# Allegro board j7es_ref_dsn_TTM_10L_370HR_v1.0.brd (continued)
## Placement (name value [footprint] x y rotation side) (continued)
R1125  10K  [R402-25]  159.64 132.83 90 bottom
R1126  10K  [R402-25]  158.62 132.83 90 bottom
R1127  47  [R402-25]  194.56 118.23 270 bottom
R1130  40.2K  [R402-25]  194.06 116.58 180 bottom
R1131  1K  [R402-25]  151.76 10.4 90 bottom
R1132  10K  [R402-25]  192.41 117.08 90 bottom
R1133  158K  [R402-25]  163.32 127.37 90 bottom
R1134  10K  [R402-25]  159.13 129.28 0 bottom
R1135  10K  [R402-25]  191.26 117.08 90 bottom
R1136  3.01  [R402-25]  186.56 123.69 270 bottom
R1137  3.0  [R402-25]  185.93 118.99 0 bottom
R1138  3.01  [R402-25]  185.42 123.69 270 bottom
R1139  0  [R402-25]  189.99 97.14 90 bottom
R1140  0  [R402-25]  191.13 97.14 270 bottom
R1141  100K  [R402-25]  195.83 100.32 0 bottom
R1142  10K  [R402-25]  195.71 102.1 0 bottom
R1143  NP  [R402-25]  196.72 103.62 0 bottom
R1144  0  [R402-25]  188.98 104.51 270 bottom
R1145  3.3  [R402-25]  190.12 104.51 90 bottom
R1146  10K  [R402-25]  195.07 104.51 90 bottom
R1147  42.2K  [R402-25]  192.15 105.78 270 bottom
R1152  1.0  [R1206-40X70]  183.26 109.34 90 bottom
R1164  10K  [R402-25]  140.33 148.33 0 top
R1188  47K  [R402-25]  152.15 87.37 180 bottom
R1189  47K  [R402-25]  152.15 90.03 180 bottom
R1190  47K  [R402-25]  152.02 83.05 180 bottom
R1191  47K  [R402-25]  151.13 80.25 0 bottom
R1192  1K  [R402-25]  150.88 85.97 0 bottom
R1196  47K  [R402-25]  149.35 83.05 180 bottom
R1197  47K  [R402-25]  149.22 90.03 180 bottom
R1198  47K  [R402-25]  149.1 80.25 180 bottom
R1200  47K  [R402-25]  148.21 85.33 180 bottom
R1201  47K  [R402-25]  148.21 87.37 0 bottom
R1203  0  [R402-25]  146.81 84.7 270 bottom
R1204  NP  [R402-25]  145.8 84.7 90 bottom
R1205  0  [R402-25]  52.58 58.54 0 bottom
R1206  4.7K  [R402-25]  52.58 59.81 0 bottom
R1207  4.7K  [R402-25]  52.58 61.08 0 bottom
R1208  4.7K  [R402-25]  52.58 54.6 0 bottom
R1209  4.7K  [R402-25]  52.58 57.27 0 bottom
R1219  4.7K  [R402-25]  46.23 55.36 180 bottom
R1221  4.7K  [R402-25]  43.56 56.63 180 bottom
R2008  1K  [R201-6P6SPC]  33.53 24.25 270 bottom
R2020  2.49K  [R402-25]  49.4 36.06 90 top
R2021  2.49K  [R402-25]  48.13 36.06 90 top
R2024  27  [R402-25]  38.1 38.34 0 top
R2025  1K  [R402-25]  27.56 41.14 270 top
R2026  NP-0  [R402-25]  52.58 43.8 90 top
R2027  1K  [R402-25]  27.56 43.8 90 top
R2030  27  [R402-25]  38.1 46.6 0 top
R2032  10K  [R402-25]  28.32 48.12 180 top
R2058  NP-0  [R402-25]  46.86 26.41 180 top
R2059  NP-0  [R402-25]  46.86 27.68 180 top
R2098  62  [R1206-40X70]  29.08 29.33 0 bottom
R2099  3.32K  [R402-25]  32.38 29.71 90 bottom
R2100  100  [R402-25]  33.66 29.71 90 bottom
R2101  33.2K  [R402-25]  34.92 29.71 90 bottom
R2102  100  [R402-25]  42.54 31.87 270 bottom
R2103  10K  [R402-25]  42.54 29.71 90 bottom
R2104  62  [R1206-40X70]  29.08 31.61 180 bottom
R2105  10K  [R402-25]  34.92 32.37 90 bottom
R2106  100  [R402-25]  32.38 35.04 270 bottom
R2107  100K  [R402-25]  33.66 35.04 90 bottom
R2108  100  [R402-25]  34.92 35.04 270 bottom
R2109  100  [R402-25]  37.46 35.04 90 bottom
R2110  100  [R402-25]  41.27 35.04 90 bottom
R2111  1.5K  [R402-25]  50.67 48 180 bottom
R2112  3.32K  [R402-25]  44.32 44.19 270 bottom
R2113  3.32K  [R402-25]  45.47 44.19 270 bottom
R2114  3.32K  [R402-25]  46.61 44.19 270 bottom
R2115  240  [R402-25]  50.55 45.71 90 bottom
R2116  3.32K  [R402-25]  51.56 45.71 90 bottom
R3058  4.7K  [RES0402_0-5]  91.24 36.85 180 top
R3059  1.87K_1%  [RES0402_0-5]  91.24 35.36 180 top
R3060  10K  [RES0402_0-5]  95.94 23.62 270 top
R3061  100K  [RES0402_0-5]  128.65 20.1 180 top
R3062  100K  [RES0402_0-5]  130.68 20.1 180 top
R3065  41.2K_1%  [RES0402_0-5]  103.89 16.79 90 top
R3066  41.2K_1%  [RES0402_0-5]  111.51 16.28 90 top
R3067  30.9K_1%  [RES0402_0-5]  112.65 16.28 270 top
R3102  0E  [RES0402_0-5]  99.57 23.48 0 bottom
R3103  0E  [RES0402_0-5]  102.21 23.03 90 bottom
R3104  0E  [RES0402_0-5]  100.97 23.03 90 bottom
R3105  0E  [RES0402_0-5]  115.21 21.95 0 bottom
R3110  10K  [RES0402_0-5]  105.03 16.79 270 bottom
R3111  30.9K_1%  [RES0402_0-5]  103.89 16.79 270 bottom
R3112  61.9K_1%  [RES0402_0-5]  112.65 16.28 270 bottom
R3113  30.1K_1%  [RES0402_0-5]  111.51 16.28 90 bottom
R3114  4.7K  [RES0402_0-5]  106.4 15.98 90 bottom
R3115  0E  [RES0402_0-5]  105.94 14.48 0 bottom
R3118  0E  [RES0402_0-5]  133.49 13.23 90 bottom
R3119  0E  [RES0402_0-5]  132.35 13.23 90 bottom
R3121  100K  [RES0402_0-5]  130.49 12.7 0 bottom
R3122  10K  [R402-25]  151.51 132.96 0 top
R3123  10K  [R402-25]  151.51 134.36 0 top
R3124  49.9  [R402-25]  72.52 19.04 0 bottom
R3125  2K  [R402-25]  85.47 5.7 270 bottom
R3126  4.02K  [R402-25]  64.01 13.96 180 bottom
R3127  2K  [R402-25]  68.71 5.58 270 bottom
R3128  49.9  [R402-25]  65.53 17.26 270 bottom
R3129  4.02K  [R402-25]  47.37 13.83 180 bottom
R3130  2K  [R402-25]  52.07 5.45 270 bottom
R3131  49.9  [R402-25]  62.48 17.26 270 bottom
R3132  4.02K  [R402-25]  30.73 13.83 180 bottom
R3133  2K  [R402-25]  35.56 5.45 270 bottom
R3134  49.9  [R402-25]  56.39 20.06 180 bottom
R3135  0  [R402-25]  52.58 55.62 0 bottom
R3136  0E  [RES0402_0-5]  66.67 49.65 270 top
R3137  0E  [RES0402_0-5]  80.26 49.39 270 bottom
R3138  10K_1%  [RES0201_0-5]  79.25 49.27 90 bottom
R3139  10K_1%  [RES0201_0-5]  77.22 49.27 90 bottom
R3140  10K_1%  [RES0201_0-5]  81.28 49.27 90 bottom
R3141  47K  [R402-25]  154.31 91.3 0 bottom
R3142  22E_1%  [RES0402_0-5]  152.15 91.3 0 bottom
R3143  100  [R402-25]  46.86 57.65 0 bottom
R3144  DNI  [RES0402_0-5]  82.8 104.13 0 bottom
R3145  DNI  [RES0402_0-5]  132.08 84.32 0 top
R3146  DNI  [RES0402_0-5]  132.08 83.3 180 top
R3147  10K_1%  [RES0402_0-5]  127.89 108.45 0 top
R3148  DNI  [RES0402_0-5]  55.63 95.49 180 top
R3149  0E  [RES0402_0-5]  57.66 95.49 0 top
R3150  DNI  [RES0402_0-5]  55.63 98.16 180 top
R3151  0E  [RES0402_0-5]  57.66 98.16 0 top
R*  -  [unnamed#4]  115.82 18.31 180 top
RJ1000  0  [JMP402-25]  177.29 133.85 270 top
RJ1001  1000pF  [JMP402-25]  182.88 115.69 0 top
RJ1013  1000pF  [JMP402-25]  155.32 54.85 180 top
RJ1025  0.A  [JMP402-25]  48.77 56.63 0 bottom
RJ2008  3.32K.A  [JMP402-25]  37.46 31.49 90 bottom
SW2001  PB_SW  [SW4-7914G]  32.38 21.58 180 top
TP35  -  [TP40_SMD]  111 40.76 270 top
TP36  -  [TP40_SMD]  112.9 40.76 270 top
TP37  -  [TP40_SMD]  124.33 36.95 270 top
TP38  -  [TP40_SMD]  124.33 39.61 270 top
TP39  -  [TP40_SMD]  126.24 36.95 270 top
TP40  -  [TP40_SMD]  126.24 39.61 270 top
TP42  -  [TP40_SMD]  116.71 38.22 270 top
TP43  -  [TP40_SMD]  114.81 38.22 270 top
TP105  -  [TP40_SMD]  132.97 78.86 90 top
TP108  -  [TP40_SMD]  53.59 108.19 180 top
TP109  -  [TP40_SMD]  53.59 105.65 180 top
TP115  -  [TP40_SMD]  53.47 100.57 0 top
TP116  -  [TP40_SMD]  41.78 58.66 270 top
TP117  -  [TP40_SMD]  40.77 52.82 0 top
TP127  -  [TP40_SMD]  70.68 74.6 0 top
TP128  -  [TP40_SMD]  125.86 108.45 0 top
TP1000  TP  [TP-30RD13]  179.32 93.84 0 top
TP1001  TP  [TP-30RD13]  197.23 127.12 0 top
TP1002  TP  [TP-30RD13]  171.07 129.66 0 top
TP1003  TP  [TP-30RD13]  157.73 130.29 0 top
TP1004  TP  [TP-30RD13]  159.38 43.04 180 top
TP1005  TP  [TP-30RD13]  185.93 115.43 0 top
TP1006  TP  [TP-30RD13]  186.56 72.38 0 top
TP1008  TP  [TP-30RD13]  179.32 60.44 90 top
TP1010  TP  [TP-30RD13]  195.71 109.59 270 top
TP1012  TP  [TP-30RD13]  184.28 49.65 90 top
TP1013  TP  [TP-30RD13]  164.34 46.85 0 top
TP1016  SMT-TP  [TP1-70X135]  179.58 45.07 90 top
TP1018  TP  [TP-30RD13]  138.56 148.33 0 top
TP1037  TP  [TP-30RD13]  21.08 21.58 0 top
TP1040  TP  [TP-30RD13]  146.3 68.95 0 top
TP2000  TP  [TP-30RD13]  43.69 37.33 90 top
TP3006  -  [TP40_SMD]  97.96 24.01 0 top
TP3014  -  [TP40_SMD]  99.79 25.73 180 bottom
TP3015  -  [TP40_SMD]  102.36 52.69 0 top
TP3016  -  [TP40_SMD]  78.99 125.97 0 top
TP3017  -  [TP40_SMD]  53.47 102.99 0 top
TP3018  -  [TP40_SMD]  76.83 125.97 0 top
TP3019  -  [TP40_SMD]  136.52 84.7 0 top
TP3020  -  [TP40_SMD]  53.47 95.49 0 top
TP3021  -  [TP40_SMD]  53.47 98.16 0 top
TPX1  TP_VIA_MEM0  [TP1-18RD8]  51.31 90.29 0 top
TPX2  TP_VIA_MEM0  [TP1-18RD8]  52.58 86.48 0 top
TPX3  TP_VIA_MEM0  [TP1-18RD8]  48.77 83.94 0 top
TPX4  TP_VIA_MEM0  [TP1-18RD8]  48.77 85.21 0 top
TPX5  TP_VIA_MEM0  [TP1-18RD8]  48.77 81.4 0 top
TPX6  TP_VIA_MEM0  [TP1-18RD8]  50.04 78.86 0 top
TPX7  TP_VIA_MEM0  [TP1-18RD8]  46.23 78.86 0 top
TPX10  TP_VIA_MEM0  [TP1-18RD8]  50.04 77.59 0 top
TPX11  TP_VIA_MEM0  [TP1-18RD8]  65.28 62.35 0 top
TPX12  TP_VIA_MEM0  [TP1-18RD8]  52.58 75.05 0 top
TPX13  TP_VIA_MEM0  [TP1-18RD8]  60.2 50.28 0 top
TPX14  TP_VIA_MEM0  [TP1-18RD8]  62.74 57.27 0 top
TPX15  TP_VIA_MEM0  [TP1-18RD8]  65.28 57.27 0 top
TPX16  TP_VIA_MEM0  [TP1-18RD8]  60.83 69.33 0 top
TPX17  TP_VIA_MEM0  [TP1-18RD8]  39.88 61.71 0 top
TPX18  TP_VIA_MEM0  [TP1-18RD8]  38.61 63.62 0 top
TPX21  TP_VIA_MEM0  [TP1-18RD8]  65.28 48.38 0 top
TPX25  TP_VIA_MEM0  [TP1-18RD8]  47.5 90.29 0 top
TPX26  TP_VIA_MEM0  [TP1-18RD8]  47.5 89.02 0 top
TPX27  TP_VIA_MEM0  [TP1-18RD8]  53.85 85.21 0 top
TPX28  TP_VIA_MEM0  [TP1-18RD8]  48.77 87.75 0 top
TPX29  TP_VIA_MEM0  [TP1-18RD8]  51.31 81.4 0 top
TPX30  TP_VIA_MEM0  [TP1-18RD8]  50.04 81.4 0 top
TPX31  TP_VIA_MEM0  [TP1-18RD8]  50.04 83.94 0 top
TPX32  TP_VIA_MEM0  [TP1-18RD8]  53.85 81.4 0 top
TPX34  TP_VIA_MEM0  [TP1-18RD8]  47.5 78.86 0 top
TPX36  TP_VIA_MEM0  [TP1-18RD8]  56.64 71.87 0 top
TPX37  TP_VIA_MEM0  [TP1-18RD8]  64.01 62.35 0 top
TPX38  TP_VIA_MEM0  [TP1-18RD8]  37.34 64.89 0 top
TPX39  TP_VIA_MEM0  [TP1-18RD8]  70.36 62.35 0 top
TPX41  TP_VIA_MEM0  [TP1-18RD8]  55.12 75.05 0 top
TPX42  TP_VIA_MEM0  [TP1-18RD8]  64.01 60.44 0 top
TPX43  TP_VIA_MEM0  [TP1-18RD8]  61.47 60.44 0 top
TPX44  TP_VIA_MEM0  [TP1-18RD8]  61.47 57.27 0 top
TPX48  TP_VIA_MEM0  [TP1-18RD8]  66.55 52.19 90 top
TPX49  TP_VIA_MEM0  [TP1-18RD8]  48.77 90.29 0 top
TPX50  TP_VIA_MEM0  [TP1-18RD8]  50.04 90.29 0 top
TPX53  TP_VIA_MEM0  [TP1-18RD8]  46.23 85.21 0 top
TPX54  TP_VIA_MEM0  [TP1-18RD8]  53.85 83.94 0 top
TPX55  TP_VIA_MEM0  [TP1-18RD8]  53.85 80.13 0 top
TPX56  TP_VIA_MEM0  [TP1-18RD8]  51.31 82.67 0 top
TPX58  TP_VIA_MEM0  [TP1-18RD8]  47.5 80.13 0 top
TPX59  TP_VIA_MEM0  [TP1-18RD8]  53.85 77.59 0 top
TPX60  TP_VIA_MEM0  [TP1-18RD8]  57.66 75.05 0 top
TPX61  TP_VIA_MEM0  [TP1-18RD8]  64.01 48.38 0 top
TPX62  TP_VIA_MEM0  [TP1-18RD8]  70.99 66.16 0 top
TPX63  TP_VIA_MEM0  [TP1-18RD8]  47.5 82.67 0 top
TPX64  TP_VIA_MEM0  [TP1-18RD8]  60.2 46.47 0 top
TPX65  TP_VIA_MEM0  [TP1-18RD8]  38.61 64.89 0 top
TPX66  TP_VIA_MEM0  [TP1-18RD8]  65.28 58.54 0 top
TPX67  TP_VIA_MEM0  [TP1-18RD8]  71.63 51.55 0 top
TPX68  TP_VIA_MEM0  [TP1-18RD8]  79.76 61.46 0 top
TPX69  TP_VIA_MEM0  [TP1-18RD8]  61.47 52.19 0 top
TPX70  TP_VIA_MEM0  [TP1-18RD8]  61.47 50.28 0 top
TPX72  TP_VIA_MEM0  [TP1-18RD8]  53.85 87.75 0 top
TPX73  TP_VIA_MEM0  [TP1-18RD8]  47.5 86.48 0 top
TPX74  TP_VIA_MEM0  [TP1-18RD8]  48.77 80.13 0 top
TPX75  TP_VIA_MEM0  [TP1-18RD8]  51.31 89.02 0 top
TPX76  TP_VIA_MEM0  [TP1-18RD8]  47.5 85.21 0 top
TPX77  TP_VIA_MEM0  [TP1-18RD8]  46.23 83.94 0 top
TPX78  TP_VIA_MEM0  [TP1-18RD8]  52.58 85.21 0 top
TPX79  TP_VIA_MEM0  [TP1-18RD8]  47.5 81.4 0 top
TPX80  TP_VIA_MEM0  [TP1-18RD8]  62.74 46.47 0 top
TPX81  TP_VIA_MEM0  [TP1-18RD8]  48.77 78.86 0 top
TPX82  TP_VIA_MEM0  [TP1-18RD8]  46.23 75.05 0 top
TPX83  TP_VIA_MEM0  [TP1-18RD8]  53.85 76.32 0 top
TPX84  TP_VIA_MEM0  [TP1-18RD8]  51.31 75.05 0 top
TPX85  TP_VIA_MEM0  [TP1-18RD8]  68.45 64.89 0 top
TPX86  TP_VIA_MEM0  [TP1-18RD8]  69.72 64.89 0 top
TPX87  TP_VIA_MEM0  [TP1-18RD8]  64.01 46.47 0 top
TPX88  TP_VIA_MEM0  [TP1-18RD8]  62.74 48.38 0 top
TPX89  TP_VIA_MEM0  [TP1-18RD8]  39.88 64.89 0 top
TPX90  TP_VIA_MEM0  [TP1-18RD8]  62.74 52.19 0 top
TPX92  TP_VIA_MEM0  [TP1-18RD8]  39.88 58.66 0 top
TPX93  TP_VIA_MEM0  [TP1-18RD8]  65.28 52.19 0 top
TPX94  TP_VIA_MEM0  [TP1-18RD8]  62.74 50.28 0 top
TPX95  TP_VIA_MEM0  [TP1-18RD8]  61.47 48.38 0 top
TPX97  TP_VIA_MEM0  [TP1-18RD8]  47.5 87.75 0 top
TPX98  TP_VIA_MEM0  [TP1-18RD8]  50.04 85.21 0 top
TPX99  TP_VIA_MEM0  [TP1-18RD8]  50.04 86.48 0 top
TPX100  TP_VIA_MEM0  [TP1-18RD8]  52.58 87.75 0 top
TPX101  TP_VIA_MEM0  [TP1-18RD8]  51.31 87.75 0 top
TPX102  TP_VIA_MEM0  [TP1-18RD8]  50.04 82.67 0 top
TPX103  TP_VIA_MEM0  [TP1-18RD8]  51.31 83.94 0 top
TPX104  TP_VIA_MEM0  [TP1-18RD8]  52.58 82.67 0 top
TPX105  TP_VIA_MEM0  [TP1-18RD8]  34.8 49.65 0 top
TPX106  TP_VIA_MEM0  [TP1-18RD8]  37.34 49.65 0 top
TPX107  TP_VIA_MEM0  [TP1-18RD8]  61.47 46.47 0 top
TPX108  TP_VIA_MEM0  [TP1-18RD8]  36.07 49.65 0 top
TPX109  TP_VIA_MEM0  [TP1-18RD8]  56.39 75.05 0 top
TPX110  TP_VIA_MEM0  [TP1-18RD8]  50.04 76.32 0 top
TPX111  TP_VIA_MEM0  [TP1-18RD8]  68.45 66.16 0 top
TPX112  TP_VIA_MEM0  [TP1-18RD8]  43.05 74.41 0 top
TPX113  TP_VIA_MEM0  [TP1-18RD8]  53.85 48.38 0 top
TPX114  TP_VIA_MEM0  [TP1-18RD8]  67.82 58.54 0 top
TPX115  TP_VIA_MEM0  [TP1-18RD8]  71.63 62.35 0 top
TPX116  TP_VIA_MEM0  [TP1-18RD8]  64.01 57.27 0 top
TPX117  TP_VIA_MEM0  [TP1-18RD8]  60.2 52.19 0 top
TPX118  TP_VIA_MEM0  [TP1-18RD8]  64.01 52.19 0 top
TPX121  TP_VIA_MEM0  [TP1-18RD8]  60.2 48.38 0 top
TPX122  TP_VIA_MEM0  [TP1-18RD8]  46.23 89.02 0 top
TPX123  TP_VIA_MEM0  [TP1-18RD8]  53.85 86.48 0 top
TPX124  TP_VIA_MEM0  [TP1-18RD8]  46.23 80.13 0 top
TPX125  TP_VIA_MEM0  [TP1-18RD8]  52.58 89.02 0 top
TPX126  TP_VIA_MEM0  [TP1-18RD8]  48.77 89.02 0 top
TPX127  TP_VIA_MEM0  [TP1-18RD8]  46.23 86.48 0 top
TPX128  TP_VIA_MEM0  [TP1-18RD8]  50.04 80.13 0 top
TPX129  TP_VIA_MEM0  [TP1-18RD8]  47.5 83.94 0 top
TPX130  TP_VIA_MEM0  [TP1-18RD8]  52.58 77.59 0 top
TPX131  TP_VIA_MEM0  [TP1-18RD8]  33.53 49.65 0 top
TPX132  TP_VIA_MEM0  [TP1-18RD8]  52.58 78.86 0 top
TPX133  TP_VIA_MEM0  [TP1-18RD8]  46.23 76.32 0 top
TPX134  TP_VIA_MEM0  [TP1-18RD8]  51.31 76.32 0 top
TPX135  TP_VIA_MEM0  [TP1-18RD8]  48.77 75.05 0 top
TPX136  TP_VIA_MEM0  [TP1-18RD8]  66.55 62.35 0 top
TPX137  TP_VIA_MEM0  [TP1-18RD8]  64.01 50.28 0 top
TPX138  TP_VIA_MEM0  [TP1-18RD8]  41.78 73.14 0 top
TPX139  TP_VIA_MEM0  [TP1-18RD8]  66.55 58.54 0 top
TPX140  TP_VIA_MEM0  [TP1-18RD8]  69.09 62.35 0 top
TPX147  TP_VIA_MEM0  [TP1-18RD8]  89.28 109.59 0 top
TPX148  TP_VIA_MEM0  [TP1-18RD8]  48.77 82.67 0 top
TPX149  TP_VIA_MEM0  [TP1-18RD8]  51.31 85.21 0 top
TPX150  TP_VIA_MEM0  [TP1-18RD8]  50.04 89.02 0 top
TPX151  TP_VIA_MEM0  [TP1-18RD8]  48.77 86.48 0 top
TPX152  TP_VIA_MEM0  [TP1-18RD8]  52.58 80.13 0 top
TPX153  TP_VIA_MEM0  [TP1-18RD8]  51.31 80.13 0 top
TPX154  TP_VIA_MEM0  [TP1-18RD8]  46.23 82.67 0 top
TPX155  TP_VIA_MEM0  [TP1-18RD8]  51.31 78.86 0 top
TPX156  TP_VIA_MEM0  [TP1-18RD8]  36.07 51.55 0 top
TPX157  TP_VIA_MEM0  [TP1-18RD8]  53.85 78.86 0 top
TPX158  TP_VIA_MEM0  [TP1-18RD8]  47.5 76.32 0 top
TPX159  TP_VIA_MEM0  [TP1-18RD8]  51.31 77.59 0 top
TPX160  TP_VIA_MEM0  [TP1-18RD8]  46.23 77.59 0 top
TPX161  TP_VIA_MEM0  [TP1-18RD8]  47.5 75.05 0 top
TPX162  TP_VIA_MEM0  [TP1-18RD8]  70.99 64.89 0 top
TPX163  TP_VIA_MEM0  [TP1-18RD8]  43.05 71.87 0 top
TPX164  TP_VIA_MEM0  [TP1-18RD8]  55.37 70.73 0 top
TPX165  TP_VIA_MEM0  [TP1-18RD8]  67.82 57.27 0 top
TPX166  TP_VIA_MEM0  [TP1-18RD8]  65.28 60.44 0 top
TPX167  TP_VIA_MEM0  [TP1-18RD8]  72.9 62.35 0 top
TPX168  TP_VIA_MEM0  [TP1-18RD8]  67.82 52.19 0 top
TPX173  TP_VIA_MEM0  [TP1-18RD8]  46.23 87.75 0 top
TPX174  TP_VIA_MEM0  [TP1-18RD8]  52.58 83.94 0 top
TPX175  TP_VIA_MEM0  [TP1-18RD8]  53.85 89.02 0 top
TPX176  TP_VIA_MEM0  [TP1-18RD8]  51.31 86.48 0 top
TPX177  TP_VIA_MEM0  [TP1-18RD8]  50.04 87.75 0 top
TPX178  TP_VIA_MEM0  [TP1-18RD8]  46.23 81.4 0 top
TPX179  TP_VIA_MEM0  [TP1-18RD8]  53.85 82.67 0 top
TPX180  TP_VIA_MEM0  [TP1-18RD8]  52.58 81.4 0 top
TPX181  TP_VIA_MEM0  [TP1-18RD8]  52.58 76.32 0 top
TPX182  TP_VIA_MEM0  [TP1-18RD8]  53.85 75.05 0 top
TPX183  TP_VIA_MEM0  [TP1-18RD8]  48.77 77.59 0 top
TPX184  TP_VIA_MEM0  [TP1-18RD8]  48.77 76.32 0 top
TPX185  TP_VIA_MEM0  [TP1-18RD8]  50.04 75.05 0 top
TPX186  TP_VIA_MEM0  [TP1-18RD8]  47.5 77.59 0 top
TPX187  TP_VIA_MEM0  [TP1-18RD8]  37.34 51.55 0 top
TPX188  TP_VIA_MEM0  [TP1-18RD8]  43.05 73.14 0 top
TPX189  TP_VIA_MEM0  [TP1-18RD8]  58.29 70.09 0 top
TPX190  TP_VIA_MEM0  [TP1-18RD8]  66.55 57.27 0 top
TPX191  TP_VIA_MEM0  [TP1-18RD8]  74.17 62.35 0 top
TPX192  TP_VIA_MEM0  [TP1-18RD8]  37.34 53.46 0 top
TPX193  TP_VIA_MEM0  [TP1-18RD8]  36.07 53.46 0 top
TPX203  TP_VIA_MEM0  [TP1-18RD8]  112.9 115.05 0 top
TPX204  TP_VIA_MEM0  [TP1-18RD8]  152.27 76.32 0 top
TPX205  TP_VIA_MEM0  [TP1-18RD8]  157.35 76.32 0 top
TPX206  TP_VIA_MEM0  [TP1-18RD8]  53.85 90.29 0 top
TPX208  TP_VIA_MEM0  [TP1-18RD8]  155.45 71.24 0 top
TPX211  TP_VIA_MEM0  [TP1-18RD8]  65.28 46.47 0 top
TPX214  TP_VIA_MEM0  [TP1-18RD8]  37.34 57.27 0 top
TPX215  TP_VIA_MEM0  [TP1-18RD8]  62.74 60.44 0 top
TPX222  TP_VIA_MEM0  [TP1-18RD8]  149.73 76.32 0 top
TPX226  TP_VIA_MEM0  [TP1-18RD8]  151 76.32 0 top
TPX229  TP_VIA_MEM0  [TP1-18RD8]  156.72 71.24 0 top
TPX230  TP_VIA_MEM0  [TP1-18RD8]  153.92 71.24 0 top
TPX234  TP_VIA_MEM0  [TP1-18RD8]  132.46 107.56 0 top
TPX237  TP_VIA_MEM0  [TP1-18RD8]  67.18 64.89 0 top
TPX238  TP_VIA_MEM0  [TP1-18RD8]  36.07 56 0 top
TPX239  TP_VIA_MEM0  [TP1-18RD8]  97.03 39.49 0 top
TPX240  TP_VIA_MEM0  [TP1-18RD8]  96.39 39.49 0 top
TPX243  TP_VIA_MEM0  [TP1-18RD8]  112.9 113.78 0 top
TPX248  TP_VIA_MEM0  [TP1-18RD8]  145.92 74.41 0 top
TPX249  TP_VIA_MEM0  [TP1-18RD8]  144.65 76.32 0 top
TPX253  TP_VIA_MEM0  [TP1-18RD8]  66.55 60.44 0 top
TPX255  TP_VIA_MEM0  [TP1-18RD8]  151 74.41 0 top
TPX256  TP_VIA_MEM0  [TP1-18RD8]  160.53 71.24 0 top
TPX258  TP_VIA_MEM0  [TP1-18RD8]  36.07 57.27 0 top
TPX259  TP_VIA_MEM0  [TP1-18RD8]  34.8 53.46 0 top
TPX265  TP_VIA_MEM0  [TP1-18RD8]  114.17 115.05 0 top
TPX270  TP_VIA_MEM0  [TP1-18RD8]  144.65 74.41 0 top
TPX274  TP_VIA_MEM0  [TP1-18RD8]  158.62 76.32 0 top
TPX275  TP_VIA_MEM0  [TP1-18RD8]  65.28 50.28 0 top
TPX278  TP_VIA_MEM0  [TP1-18RD8]  151.64 72.51 0 top
TPX279  TP_VIA_MEM0  [TP1-18RD8]  159.26 71.24 0 top
TPX282  TP_VIA_MEM0  [TP1-18RD8]  67.82 60.44 0 top
TPX283  TP_VIA_MEM0  [TP1-18RD8]  100.84 39.49 0 top
TPX284  TP_VIA_MEM0  [TP1-18RD8]  100.2 39.49 0 top
TPX291  TP_VIA_MEM0  [TP1-18RD8]  142.88 80.63 0 top
TPX292  TP_VIA_MEM0  [TP1-18RD8]  148.46 74.41 0 top
TPX293  TP_VIA_MEM0  [TP1-18RD8]  157.99 71.24 0 top
TPX294  TP_VIA_MEM0  [TP1-18RD8]  153.54 74.41 0 top
TPX295  TP_VIA_MEM0  [TP1-18RD8]  132.59 114.8 0 top
TPX296  TP_VIA_MEM0  [TP1-18RD8]  156.08 74.41 0 top
TPX298  TP_VIA_MEM0  [TP1-18RD8]  149.73 74.41 0 top
TPX299  TP_VIA_MEM0  [TP1-18RD8]  143.51 96.38 0 top
TPX301  TP_VIA_MEM0  [TP1-18RD8]  152.27 74.41 0 top
TPX312  TP_VIA_MEM0  [TP1-18RD8]  153.54 76.32 0 top
TPX313  TP_VIA_MEM0  [TP1-18RD8]  147.19 74.41 0 top
TPX315  TP_VIA_MEM0  [TP1-18RD8]  150.37 71.24 0 top
TPX319  TP_VIA_MEM0  [TP1-18RD8]  37.34 56 0 top
TPX323  TP_VIA_MEM0  [TP1-18RD8]  52.58 90.29 0 top
TPX324  TP_VIA_MEM0  [TP1-18RD8]  39.88 63.62 90 top
TPX327  TP_VIA_MEM0  [TP1-18RD8]  95.12 39.49 0 top
TPX328  TP_VIA_MEM0  [TP1-18RD8]  94.49 39.49 0 top
TPX333  TP_VIA_MEM0  [TP1-18RD8]  167.13 81.52 270 top
TPX334  TP_VIA_MEM0  [TP1-18RD8]  167.13 82.79 270 top
TPX337  TP_VIA_MEM0  [TP1-18RD8]  147.19 76.32 0 top
TPX347  TP_VIA_MEM0  [TP1-18RD8]  84.58 29.58 0 top
TPX348  TP_VIA_MEM0  [TP1-18RD8]  83.82 29.58 0 top
TPX351  TP_VIA_MEM0  [TP1-18RD8]  167.13 80.25 270 top
TPX352  TP_VIA_MEM0  [TP1-18RD8]  167.13 78.98 270 top
TPX353  TP_VIA_MEM0  [TP1-18RD8]  167.13 77.71 270 top
TPX354  TP_VIA_MEM0  [TP1-18RD8]  167.13 76.44 270 top
TPX357  TP_VIA_MEM0  [TP1-18RD8]  145.92 76.32 0 top
TPX368  TP_VIA_MEM0  [TP1-18RD8]  98.93 39.49 0 top
TPX369  TP_VIA_MEM0  [TP1-18RD8]  98.3 39.49 0 top
TPX370  TP_VIA_MEM0  [TP1-18RD8]  100.08 129.28 0 top
TPX371  TP_VIA_MEM0  [TP1-18RD8]  99.44 129.28 0 top
TPX372  TP_VIA_MEM0  [TP1-18RD8]  107.19 112.51 0 top
TPX373  TP_VIA_MEM0  [TP1-18RD8]  105.92 112.51 0 top
TPX374  TP_VIA_MEM0  [TP1-18RD8]  92.46 129.28 0 top
TPX375  TP_VIA_MEM0  [TP1-18RD8]  91.82 129.28 0 top
TPX376  TP_VIA_MEM0  [TP1-18RD8]  95 129.28 0 top
TPX377  TP_VIA_MEM0  [TP1-18RD8]  94.36 129.28 0 top
TPX378  TP_VIA_MEM0  [TP1-18RD8]  90.68 122.04 0 top
TPX379  TP_VIA_MEM0  [TP1-18RD8]  89.41 122.04 0 top
TPX380  TP_VIA_MEM0  [TP1-18RD8]  87.38 129.28 0 top
TPX381  TP_VIA_MEM0  [TP1-18RD8]  86.74 129.28 0 top
TPX382  TP_VIA_MEM0  [TP1-18RD8]  109.09 116.96 0 top
TPX383  TP_VIA_MEM0  [TP1-18RD8]  110.36 116.96 0 top
TPX384  TP_VIA_MEM0  [TP1-18RD8]  107.19 115.69 0 top
TPX385  TP_VIA_MEM0  [TP1-18RD8]  108.46 115.69 0 top
TPX386  TP_VIA_MEM0  [TP1-18RD8]  116.08 108.07 0 top
TPX387  TP_VIA_MEM0  [TP1-18RD8]  117.35 108.07 0 top
TPX388  TP_VIA_MEM0  [TP1-18RD8]  114.17 109.34 0 top
TPX389  TP_VIA_MEM0  [TP1-18RD8]  115.44 109.34 0 top
TPX390  TP_VIA_MEM0  [TP1-18RD8]  116.46 96.76 0 top
TPX391  TP_VIA_MEM0  [TP1-18RD8]  118.74 109.08 270 top
TPX392  TP_VIA_MEM0  [TP1-18RD8]  91.31 120.77 0 top
TPX393  TP_VIA_MEM0  [TP1-18RD8]  92.58 120.77 0 top
TPX396  TP_VIA_MEM0  [TP1-18RD8]  133.22 26.79 0 top
TPX397  TP_VIA_MEM0  [TP1-18RD8]  132.46 26.79 0 top
TPX422  TP_VIA_MEM0  [TP1-18RD8]  95.12 120.77 0 top
TPX423  TP_VIA_MEM0  [TP1-18RD8]  96.39 120.77 0 top
TPX426  TP_VIA_MEM0  [TP1-18RD8]  98.93 120.77 0 top
TPX427  TP_VIA_MEM0  [TP1-18RD8]  100.2 120.77 0 top
TPX428  TP_VIA_MEM0  [TP1-18RD8]  102.74 120.77 0 top
TPX429  TP_VIA_MEM0  [TP1-18RD8]  104.01 120.77 0 top
TPX440  TP_VIA_MEM0  [TP1-18RD8]  89.92 129.28 0 top
TPX441  TP_VIA_MEM0  [TP1-18RD8]  89.28 129.28 0 top
TPX442  TP_VIA_MEM0  [TP1-18RD8]  94.49 122.04 0 top
TPX443  TP_VIA_MEM0  [TP1-18RD8]  93.22 122.04 0 top
TPX446  TP_VIA_MEM0  [TP1-18RD8]  97.54 129.28 0 top
TPX447  TP_VIA_MEM0  [TP1-18RD8]  96.9 129.28 0 top
TPX448  TP_VIA_MEM0  [TP1-18RD8]  102.11 122.04 0 top
TPX449  TP_VIA_MEM0  [TP1-18RD8]  100.84 122.04 0 top
TPX450  TP_VIA_MEM0  [TP1-18RD8]  97.03 122.04 0 top
TPX451  TP_VIA_MEM0  [TP1-18RD8]  98.3 122.04 0 top
TPX454  TP_VIA_MEM0  [TP1-18RD8]  105.92 113.78 0 top
TPX455  TP_VIA_MEM0  [TP1-18RD8]  104.65 113.78 0 top
TPX460  TP_VIA_MEM0  [TP1-18RD8]  154.81 74.41 0 top
U6  TPS22965NDSGR  [WSON8_19-68_80X80_0-8]  157.66 109.57 180 top
U9  J721E_181212  [FCBGA827_31-49_950X950_2-8]  98.65 71.74 180 top
U11  MT53D1024M32D4DT  [WFBGA200_MT53DDS_400X570_1]  126.93 66.46 180 top
U18  SN74LVC1G08DBVRE4  [SOT23-5]  70.61 45.33 180 top
U22  TPS22965NDSGR  [WSON8_19-68_80X80_0-8]  63.58 102.38 270 bottom
U24  MT35XU512ABA1G12-0AUT  [TPBGA24_39-37_240X320_1-2]  79.25 45.96 180 bottom
U27  TPS659413  [VQFN56_19-68_320X320_0-9_EP6]  131.32 97.4 270 top
U29  TPS659411  [VQFN56_19-68_320X320_0-9_EP6]  76.45 106.42 180 top
U103  NVMFS4C05NT1G  [DFN5_NTMFS4835N_240X200_1-1]  159.65 101.94 0 top
U129  74CBTLV1G125CRG4  [DCK-5]  56.39 53.46 270 top
U130  74CBTLV1G125CRG4  [DCK-5]  56.39 56 90 top
U131  74CBTLV1G125CRG4  [DCK-5]  56.39 50.92 270 top
U1000  tpd4e05u06-q1  [DQA-PSON10]  180.47 139.18 180 bottom
U1001  TPS254900-Q1  [RVC20]  173.61 132.45 0 top
U1002  TPD3S716-Q1  [SSOP-16]  161.04 130.04 180 top
U1005  LM53603-Q1  [PWP16-14X70-PAD]  188.98 119.37 270 top
U1006  LM74610  [DGK8-14X70]  165.86 20.31 0 top
U1007  LM5141-Q1  [RGE24-11X28-4MM]  192.53 101.34 270 top
U1008  LM5175-Q1  [PWP28-14X70]  173.74 55.11 0 top
U1011  24WC256  [SO8-25X75-295]  139.19 142.61 0 top
U1017  MTFC32GAKAEDQ-AIT  [BGA100_1MM]  153.16 85.21 270 top
U1022  TPS61252  [DSG8-11X20]  23.11 16.25 180 top
U1027  LMR23625CF-Q1  [DDA8-PAD]  152.65 60.06 270 top
U1033  SN74LVC1G125DCKR  [DCK-5]  149.73 93.46 270 bottom
U2007  TCAN1043D-Q1  [SO14-25X75]  37.46 32.37 180 top
U2010  TPD1E10B06DPY  [DPY]  36.83 39.74 180 top
U2011  DP83TC811-Q1  [RND36-24X10]  47.24 41.77 180 top
U2012  TPD1E10B06DPY  [DPY]  36.83 45.07 180 top
U2023  TPS72010QDRVR  [DRV6-12X30]  53.21 30.22 270 top
U3011  TPS1H100AQPWPRQ1  [HTSSOP14_TPS1H100-Q1_180X200_1-2]  96.84 29.2 90 top
U3019  PDS90UB941ASRTDTQ1  [QFN64_19-68_360X360_0-9_EP6]  108.58 23.27 180 bottom
U3020  25.000MHz  [OSC4_ASDMB_100X85_SMD_0-9]  100.19 20.36 90 bottom
U3021  tpd4e05u06-q1  [DQA-PSON10]  155.83 139.18 180 bottom
U3022  DS90UB960Q  [RTD0064F]  64.52 25.9 0 bottom
Y1  22.5792MHz  [XTAL4_ABM10W_100X80_SMD_0-6]  74.8 73.27 0 top
Y2  32.768KHz  [XTAL_ABS07AIG_130X60_SMD_0-9]  74.8 69.46 0 top
Y3  19.200MHz  [XTAL4_ABM10W_100X80_SMD_0-6]  74.68 65.65 0 top
Y6  32.768KHz  [XTAL_ECS-32_130X60_SMD_0-9]  137.82 88.83 180 bottom
Y2000  25MHz/10pF  [XTAL4-ABM11]  47.5 47.87 90 top

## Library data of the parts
C26-C31 C34 C43-C45 C47 C49 C55 C56 C60-C63 C71-C73 C79 C81-C83 C85-C90 C92 C94 C96 C97 C101 C102 C110-C112 C114 C120 C121 C124 C125 C128 C130-C133 C135 C136 C141 C155-C159 C162-C165 C169 C173 C177 C178 C186 C188-C190 C200 C202-C206 C208 C210-C227 C236 C237 C239 C243 C245-C247 C252-C259 C261-C271 C273-C294 C297-C346 C350-C400 C402-C404 C410 C413-C423 C425 C427-C446 C449-C453 C481-C514 C516-C546 C571 C1019 C1034 C1055 C1060 C1064 C1065 C1069 C1070 C1161 C2084 C2087 C2115 C2117-C2125 C2128 C2129 C3049-C3054 C3056-C3058 C3061-C3063 C3067-C3071 C3096-C3098 C3100-C3103 C3105-C3111 C3114 C3116 C3118 C3119 C3121-C3123 C3146-C3149 = CAP
C32 C33 C37 C38 C41 C42 C53 C54 C57-C59 C64-C70 C78 C80 C84 C91 C93 C95 C98-C100 C106 C107 C118 C119 C149 C160 C161 C166-C168 C179-C182 C184 C192 C193 C197 C198 C260 C272 = CAP_NFM
C35 C46 C48 C50 C104 C105 C122 C185 C187 C199 C201 C238 C242 C244 C249 C295 C296 C348 C349 C405 C411 C570 C1008 C1012 C1020-C1025 C1190 C1239 C1241 C1249 C2023 C2035 C2037 C2085 C2086 C3126 C3128 C3130 C3134 C3136 C3140 C3142 = CAP: Tolerance: X; User Part Number: X
C228 C234 C1059 C2116 C3124 C3125 C3127 C3129 C3131-C3133 C3135 C3137-C3139 C3141 C3143 C3144 = CAP: User Part Number: USERPART#; Tolerance: TOLERANCE
C1003 C1005 C1006 C1015 C1037 C1046 C1049 C1063 C1200 C2028-C2031 = CAP NP: Tolerance: X; User Part Number: X
C1004 C1009 C1011 C1016 C1028 C1029 C1040 C1182 C1183 = CAP NP_0: Tolerance: X; User Part Number: X
C1007 C1039 C1047 C1050 C1052 C1061 C1062 C1194 C1204 C1245 C2027 C2034 C3145 = CAP NP
C1010 C1030-C1032 C1035 C1036 C1187 C1201 C1202 = CAP NP_0: User Part Number: X; Tolerance: X
C1017 C1018 C1197 C1238 = Cap 100nF Cermc 16V 10% 603_4
C1026 = CAP_AM_0402_0.1uf_x7r_16v_10%_X: User Part Number: USERPART#; Tolerance: TOLERANCE
C1027 = CAP_AM_0402_0.1uf_x7r_16v_10%_X: Tolerance: X; User Part Number: X
C1033 C1041 C1051 = CAP NP_2
C1038 C1199 C2126 C2127 = CAP NP_3
C1043 = CAP NP_2: Tolerance: X; User Part Number: X
C1044 C1045 C1205 = CAP NP_0: User Part Number: X; Tolerance: 20%; tolerance: 20%
C1053 = CAP_0402_220pf_x7r_50v_10%_X_SD: tolerance: +/-10%
C1071 C1191 = CAP_AM_0402_0.1uf_x7r_16v_10%_X
C1136 C1145 C1146 = CAP_AM_0805_10uf_x7r_10v_10_X: Tolerance: X; User Part Number: X
C1189 = CAP_AM_0603_0.47uf_x7r_16v_10_X: Tolerance: X; User Part Number: X
C1198 = CAP NP_0
C1209 = CAP .1 uF 10% 0603
C1240 C1242 = Cap 100nF Cermc 16V 10% 603_4: Tolerance: X; User Part Number: X
D1 = DIODE_ZENER_SOT23_13
D2 = DIODE_ZENER
D1002 = PDS5100
D1003 = DIODE ZENER: Tolerance: TOLERANCE; User Part Number: USERPART#
D1004 D1006 D1008 = DIODE SCHOTTKY_0: Tolerance: TOLERANCE; User Part Number: USERPART#
D1005 D1007 = DIODE
D1018 D1019 = Diode_SMCJ15CA
D1020 = DIODE SCHOTTKY_0: User Part Number: X; Tolerance: X
D3019-D3022 D3029-D3034 = DIODE_TPD1E05U06
D3036 = DIODE_TVS
DS1000 = LED_RED_0: Tolerance: X; User Part Number: X
FL1 FL3-FL6 FL9 FL11-FL16 FL18-FL21 FL26-FL29 FL3011-FL3014 = EMIFILTER_IND
FL1000-FL1003 FL3015 FL3019 FL3020 FL3023 FL3024 FL3028-FL3030 = DLW21SN121HQ2: User Part Number: PART#; Tolerance: TOL
FL3026 = CAP_FILTER
J1000 J1001 = 1932258-1-USB3
J1003 = 4 HEADER: User Part Number: X; Tolerance: X
J1010 = HEADER 2: Tolerance: X; User Part Number: X
J1011 = MIPI-QTH-030_1: User Part Number: PART#; Tolerance: TOL
J3003 = CON20_USB_F_TI
J3005 = CON_JACK4_EXG.0B.304
JZ2000 = Molex34826-0124: Tolerance: TOLERANCE; User Part Number: USERPART#
L1-L10 = INDUCTOR
L27 L2022 L2028 L2034 = CHOKE: User Part Number: USERPART#; Tolerance: TOLERANCE
L40 L2023 L2029 L2035 = CHOKE: Tolerance: TOLERANCE; User Part Number: USERPART#
L51 L60-L62 L2004 L2008 L2017-L2021 L2024-L2027 L2030-L2033 = FERRITE CHIP_0: Tolerance: X; User Part Number: X
L1000 = CHOKE HASH-IRON: Tolerance: TOLERANCE; User Part Number: USERPART#
L1001 = INDUCTOR IRON
L1002 = INDUCTOR IRON: Tolerance: TOLERANCE; User Part Number: USERPART#
L1003 L2005 L2007 = CHOKE HASH-IRON: Tolerance: X; User Part Number: X
L1004 = CHOKE HASH-IRON: User Part Number: USERPART#; Tolerance: TOLERANCE
L1005 L1023 = INDUCTOR IRON: Tolerance: X; User Part Number: X
L1040 = INDUCTOR IRON: User Part Number: X; Tolerance: X
L2006 = CHOKE CM_AE2002: User Part Number: USERPART#; Tolerance: TOLERANCE
M1000 M1001 = MHP93-200
P5-P8 = 59S20X-400L5-Z: Tolerance: TOLERANCE; User Part Number: USERPART#
Q13 = MOSFET N_1: Tolerance: X; User Part Number: X
Q1001 = BSS138PS: User Part Number: X; Tolerance: X
Q1002 = MOSFET_CSD16406Q3_0: User Part Number: X; Tolerance: X
Q1003-Q1008 = BSZ042N06NS: User Part Number: X; Tolerance: X
R1 R4 R20 R23 R25 R27 R37 R38 R43 R46 R54 R56 R66 R67 R74 R77 R79-R81 R84 R86-R89 R93 R105 R106 R108 R109 R113-R115 R120 R121 R124 R137 R138 R144 R149-R154 R156 R158 R161 R162 R164 R168-R171 R180 R201-R210 R213-R218 R225 R227 R228 R230 R232-R240 R242 R243 R247 R253 R264 R272 R273 R276 R277 R280 R281 R287 R288 R471-R473 R493-R496 R502-R504 R515 R522 R1106-R1108 R1188-R1191 R1196-R1198 R1200 R1201 R1203 R1204 R3058-R3062 R3065-R3067 R3102-R3105 R3110-R3115 R3118 R3119 R3121 R3136-R3142 R3144-R3151 = RESISTOR
R132 R1000-R1006 R1009 R1011 R1016-R1018 R1023-R1026 R1029 R1032 R1033 R1071 R1072 R1074 R1091 R1109 R1110 R1125-R1127 R1130 R1132-R1134 R1136-R1138 R1141-R1143 R1146 R1147 R1192 R1205-R1209 R1219 R1221 R2020 R2021 R2024 R2026 R2030 R2032 R2058 R2059 R2099-R2103 R2105-R2116 R3122 R3123 R3125-R3127 R3129 R3130 R3132 R3133 R3135 R3143 = R
R625 R2008 = R: User Part Number: USERPART#; Tolerance: TOLERANCE
R1007 R1008 R1010 R1013-R1015 R1020-R1022 R1027 R1028 R1030 R1031 R1034 R1035 R1037 R1039 R1040 R1042 R1045 R1046 R1131 R1135 R1139 R1140 R1144 R1145 R2025 R2027 = R_2
R1012 = RESISTOR: Tolerance: X; User Part Number: X
R1019 R1152 = R_2: Tolerance: X; User Part Number: X
R1036 R1038 R1041 = R_2: User Part Number: X; Tolerance: X
R1164 = R_1
R2098 R2104 = R: Tolerance: X; User Part Number: X
R3124 R3128 R3131 R3134 = R_0
RJ1000 = RJUMP3A: Tolerance: TOLERANCE; User Part Number: USERPART#
RJ1001 RJ1013 RJ1025 RJ2008 = RJUMP3: Tolerance: TOLERANCE; User Part Number: USERPART#
SW2001 = SW PUSHBUTTON_3: User Part Number: X; Tolerance: X
TP35-TP40 TP42 TP43 TP105 TP108 TP109 TP115-TP117 TP127 TP128 TP3006 TP3014-TP3021 = TESTPOINT
TP1000-TP1006 TP1008 TP1010 TP1012 TP1013 TP1018 TP1037 TP1040 = TP-30RD13: Tolerance: TOLERANCE; User Part Number: USERPART#
TP1016 = SMT-TP
TP2000 = TESTPOINT: Tolerance: TOLERANCE; User Part Number: USERPART#
TPX1-TPX7 TPX10-TPX18 TPX21 TPX25-TPX32 TPX34 TPX36-TPX39 TPX41-TPX44 TPX48-TPX50 TPX53-TPX56 TPX58-TPX70 TPX72-TPX90 TPX92-TPX95 TPX97-TPX118 TPX121-TPX140 TPX147-TPX168 TPX173-TPX193 TPX203-TPX206 TPX208 TPX211 TPX214 TPX215 TPX222 TPX226 TPX229 TPX230 TPX234 TPX237-TPX240 TPX243 TPX248 TPX249 TPX253 TPX255 TPX256 TPX258 TPX259 TPX265 TPX270 TPX274 TPX275 TPX278 TPX279 TPX282-TPX284 TPX291-TPX296 TPX298 TPX299 TPX301 TPX312 TPX313 TPX315 TPX319 TPX323 TPX324 TPX327 TPX328 TPX333 TPX334 TPX337 TPX347 TPX348 TPX351-TPX354 TPX357 TPX368-TPX393 TPX396 TPX397 TPX422 TPX423 TPX426-TPX429 TPX440-TPX443 TPX446-TPX451 TPX454 TPX455 TPX460 = TP_VIA_MEM0_0
U6 U22 = TPS22965DSGT_WSON8_0
U9 = J7ES-EVM_BGA827
U11 = MT53D1024M32D4DT_VFBGA200
U18 = SN74LVC1G08DBVRE4_SOT23-5
U24 = MT35XU512ABA1G12_TPBGA24_0
U27 U29 = TPS65941-Q1_VQFN56
U103 = MOSFET-SIS434DN
U129-U131 U1033 = SN74LVC1G125_0: User Part Number: PART#
U1000 U3021 = tpd4e05u06-q1: Tolerance: TOL; User Part Number: PART#
U1001 = TPS254900-Q1
U1002 = TPD3S716-Q1: User Part Number: USERPART#; Tolerance: TOLERANCE
U1005 = LM53603-Q1: Tolerance: X; User Part Number: X
U1006 = LM74610: User Part Number: X; Tolerance: X
U1007 = LM5141-Q1
U1008 = LM5175-Q1: Tolerance: X; User Part Number: X
U1011 = 24WC256: User Part Number: X; Tolerance: X
U1017 = MTFC32GAKAEDQ-AIT: Tolerance: TOL; User Part Number: PART#
U1022 = TPS61252: User Part Number: X; Tolerance: X
U1027 = LMR23625CF-Q1: Tolerance: X; User Part Number: X
U2007 = TCAN1043D-Q1: Tolerance: X; User Part Number: X
U2010 U2012 = TPD1E10B09: Tolerance: X; User Part Number: X
U2011 = DP83TC811-Q1
U2023 = TPS72010QDRVR: User Part Number: X; Tolerance: X
U3011 = TPS1H100A-Q1_HTSSOP14_0
U3019 = DS90UB941AS-Q1_VQFN64
U3020 = OSC4_ASDMB
U3022 = DS90UB960Q
Y1 Y3 = CRY4_ABM8G
Y2 Y6 = CRY
Y2000 = CRYSTAL 4-PIN_0

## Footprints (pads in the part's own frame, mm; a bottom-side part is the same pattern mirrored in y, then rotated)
BGA100_1MM
  round 0.508 smd: A1(-4.503,8.006) A2(-3.503,8.006) A9(3.503,8.006) A10(4.503,8.006) B1(-4.503,7.005) B10(4.503,7.005) D2(-3.503,5.004) D3(-2.502,5.004) D4(-1.501,5.004) D5(-0.5,5.004) D6(0.5,5.004) D7(1.501,5.004) D8(2.502,5.004) D9(3.503,5.004) E2(-3.503,4.003) E3(-2.502,4.003) E4(-1.501,4.003) E5(-0.5,4.003) E6(0.5,4.003) E7(1.501,4.003) E8(2.502,4.003) E9(3.503,4.003) F2(-3.503,3.002) F3(-2.502,3.002) F4(-1.501,3.002) F5(-0.5,3.002) F6(0.5,3.002) F7(1.501,3.002) F8(2.502,3.002) F9(3.503,3.002) G2(-3.503,2.002) G3(-2.502,2.002) G4(-1.501,2.002) G5(-0.5,2.002) G6(0.5,2.002) G7(1.501,2.002) G8(2.502,2.002) G9(3.503,2.002) H2(-3.503,1.001) H3(-2.502,1.001) H4(-1.501,1.001) H5(-0.5,1.001) H6(0.5,1.001) H7(1.501,1.001) H8(2.502,1.001) H9(3.503,1.001) J2(-3.503,0) J3(-2.502,0) J4(-1.501,0) J5(-0.5,0) J6(0.5,0) J7(1.501,0) J8(2.502,0) J9(3.503,0) K2(-3.503,-1.001) K3(-2.502,-1.001) K4(-1.501,-1.001) K5(-0.5,-1.001) K6(0.5,-1.001) K7(1.501,-1.001) K8(2.502,-1.001) K9(3.503,-1.001) L2(-3.503,-2.002) L3(-2.502,-2.002) L4(-1.501,-2.002) L5(-0.5,-2.002) L6(0.5,-2.002) L7(1.501,-2.002) L8(2.502,-2.002) L9(3.503,-2.002) M2(-3.503,-3.002) M3(-2.502,-3.002) M4(-1.501,-3.002) M5(-0.5,-3.002) M6(0.5,-3.002) M7(1.501,-3.002) M8(2.502,-3.002) M9(3.503,-3.002) N2(-3.503,-4.003) N3(-2.502,-4.003) N4(-1.501,-4.003) N5(-0.5,-4.003) N6(0.5,-4.003) N7(1.501,-4.003) N8(2.502,-4.003) N9(3.503,-4.003) P2(-3.503,-5.004) P3(-2.502,-5.004) P4(-1.501,-5.004) P5(-0.5,-5.004) P6(0.5,-5.004) P7(1.501,-5.004) P8(2.502,-5.004) P9(3.503,-5.004) T1(-4.503,-7.005) T10(4.503,-7.005) U1(-4.503,-8.006) U2(-3.503,-8.006) U9(3.503,-8.006) U10(4.503,-8.006)
C402-25
  round 0.635 smd: 1(-0.508,0) 2(0.508,0)
C402-25RD
  round 0.635 smd: 1(-0.508,0) 2(0.508,0)
C603-35X45
  oval 0.889x1.143 smd: 1(-0.762,0) 2(0.762,0)
C805-35X60
  oval 0.889x1.524 smd: 1(-0.965,0) 2(0.965,0)
C1206-40X70
  oval 1.016x1.778 smd: 1(-1.524,0) 2(1.524,0)
C1210-70X102
  rect 1.778x3.048 smd: 1(-1.803,0) 2(1.803,0)
CAP0201_0-5
  rect 0.356x0.33 smd: 1(-0.28,0) 2(0.28,0)
CAP300X630UP
  rect 2.032x2.032 hole 1.041: 1(-7.62,0)
  round 2.032 hole 1.041: 2(0,0)
CAP0402_0-5
  rect 0.66x0.737 smd: 1(-0.536,0) 2(0.536,0)
CAP0402_0-75
  rect 0.483x0.584 smd: 1(-0.46,0) 2(0.46,0)
CAP0603_1
  rect 0.711x0.889 smd: 1(-0.7,0) 2(0.7,0)
CAP0805_1-5
  rect 1.143x1.448 smd: 1(-0.9,0) 2(0.9,0)
CAP0805_1-25
  rect 0.94x1.346 smd: 1(-0.8,0) 2(0.8,0)
CAP1206_2
  rect 0.991x1.702 smd: 1(-1.35,0) 2(1.35,0)
CAP1210_2-75
  rect 1.448x2.794 smd: 1(-1.6,0) 2(1.6,0)
CAP-FK-D8-65X117
  rect 1.651x2.972 smd: 1(0,2.261) 2(0,-2.261)
CAP-VS-F-8383
  rect 1.27x3.81 smd: 1(0,3.099) 2(0,-3.099)
CHOKE4-AE2002
  rect 1.27x0.762 smd: 1(-2.349,0.699) 2(-2.349,-0.699) 3(2.349,-0.699) 4(2.349,0.699)
COIL-XAL40
  rect 0.914x3.708 smd: 1(-1.194,0) 2(1.194,0)
CON-1932258
  round 1.118 hole 0.711: 1(-3.5,-0.75) 2(-1,-0.75) 3(1,-0.75) 4(3.5,-0.75) 5(4,0.75) 6(2,0.75) 7(0,0.75) 8(-2,0.75) 9(-4,0.75)
  round 2.921 hole 2.311: G1(-6.57,-2.75) G2(6.57,-2.75)
CON_JACK4_D4S20G-400A5_P_R_T_10-6
  rect 1.702x1.702 hole 1.016: 1(0,0)
  round 1.702 hole 1.016: 2(0,-2) 3(2,-2) 4(2,0)
  round 2.362 hole 1.676: SH1(-3.5,3.5) SH2(-3.5,-5.5) SH3(5.5,-5.5) SH4(5.5,3.5)
CON_USB20_472720001_S_R_T_7
  round 1.346 hole 1.473 unplated: (0,-2.939)
  rect 0.305x2.388 smd: 1(5.5,7.341) 2(5,7.341) 3(4.5,7.341) 4(4,7.341) 5(3.5,7.341) 6(3,7.341) 7(2.5,7.341) 8(2,7.341) 9(1.5,7.341) 10(1,7.341) 11(0.5,7.341) 12(0,7.341) 13(-0.5,7.341) 14(-1,7.341) 15(-1.5,7.341) 16(-2,7.341) 17(-2.5,7.341) 18(-3,7.341) 19(-3.5,7.341) 20(-4,7.341)
  oval 1.346x2.997 hole 0.66x2.286: SH1(-8.25,4.741) SH2(8.25,4.741)
  oval 1.346x2.489 hole 0.66x1.778: SH3(-8.25,-2.039) SH4(8.25,-2.039)
CONN4-MSTBA
  rect 2.54x2.54 hole 1.397: 1(0,0)
  round 2.54 hole 1.397: 2(-5.08,0) 3(-10.16,0) 4(-15.24,0)
CONN-ST-FAKRA
  round 2.032 hole 1.295: 1(0,0)
  round 2.286 hole 1.473: 2(-2.54,2.54) 3(2.54,2.54) 4(-2.54,-2.54) 5(2.54,-2.54)
DCK-5
  rect 0.46x0.66 smd: 1(-0.65,-0.991) 2(0,-0.991) 3(0.65,-0.991) 4(0.65,0.991) 5(-0.65,0.991)
DDA8-PAD
  oval 0.635x1.905 smd: 1(-1.905,-2.794) 2(-0.635,-2.794) 3(0.635,-2.794) 4(1.905,-2.794) 5(1.905,2.794) 6(0.635,2.794) 7(-0.635,2.794) 8(-1.905,2.794)
  rect 3.099x2.286 smd: 9(0,0)
DFN5_NTMFS4835N_240X200_1-1
  rect 0.991x0.762 smd: 1(-2.795,1.905) 2(-2.795,0.635) 3(-2.795,-0.635) 4(-2.795,-1.905)
  custom 1.132x1.132 smd: 5(0.935,0)
DGK8-14X70
  oval 0.356x1.778 smd: 1(-0.975,-2.225) 2(-0.325,-2.225) 3(0.325,-2.225) 4(0.975,-2.225) 5(0.975,2.223) 6(0.325,2.223) 7(-0.325,2.223) 8(-0.975,2.223)
DIO_DFN0402_0-5
  rect 0.457x0.711 smd: 1(-0.34,0) 2(0.34,0)
DIO_SMC
  rect 2.21x3.099 smd: 1(-3.5,0) 2(3.5,0)
DIO_SOD323_1-1
  rect 0.914x0.508 smd: 1(-1.25,0) 2(1.25,0)
DIODE-POWERDI5
  rect 1.143x1.143 smd: ANODE1(-2.87,0.914) ANODE2(-2.87,-0.914)
  rect 4.877x3.353 smd: CATHODE(0.991,0)
DPY
  rect 0.61x0.508 smd: 1(-0.495,0) 2(0.495,0)
DQA-PSON10
  rect 0.305x0.762 smd: 1(-1,-0.487) 2(-0.5,-0.487) 4(0.5,-0.487) 5(1,-0.487) 6(1,0.487) 7(0.5,0.487) 9(-0.5,0.487) 10(-1,0.487)
  rect 0.406x0.762 smd: 3(0,-0.487) 8(0,0.487)
DRV6-12X30
  rect 0.305x0.762 smd: 1(-0.65,-1.016) 2(0,-1.016) 3(0.65,-1.016) 4(0.65,1.016) 5(0,1.016) 6(-0.65,1.016)
  rect 1.397x0.889 smd: 7(0,0)
DSG8-11X20
  rect 0.279x0.508 smd: 1(-0.75,-0.965) 2(-0.25,-0.965) 3(0.25,-0.965) 4(0.75,-0.965) 5(0.75,0.965) 6(0.25,0.965) 7(-0.25,0.965) 8(-0.75,0.965)
  rect 1.6x0.889 smd: 9(0,0)
EMI-36X15-DLW21
  rect 0.914x0.381 smd: 1(-0.838,0.406) 2(0.838,0.406) 3(0.838,-0.406) 4(-0.838,-0.406)
EMI-36X15-DLW21-RDPADS
  oval 0.914x0.381 smd: 1(-0.838,0.406) 2(0.838,0.406) 3(0.838,-0.406) 4(-0.838,-0.406)
EMIFIL_BLM18A_0603
  rect 0.991x0.991 smd: 1(-0.75,0) 2(0.75,0)
EMIFIL_BLM18P_0603_0-8
  rect 0.991x0.991 smd: 1(-0.75,0) 2(0.75,0)
EMIFIL_NFM15CC_0402_0-5
  rect 0.305x0.305 smd: 1(-0.5,0) 3(0.5,0)
  rect 0.254x0.762 smd: 2(0,0)
EMIFIL_NFM18C_0603_0-7
  rect 0.61x0.61 smd: 1(-0.8,0) 3(0.8,0)
  rect 0.406x1.219 smd: 2(0,0)
EMIFIL_NFM21P_0805
  rect 0.609x0.609 smd: 1(-1,0) 3(1,0)
  rect 0.61x1.905 smd: 2(0,0)
FCBGA827_31-49_950X950_2-8
  round 0.457 smd: A1(-11.2,11.2) A2(-10.4,11.2) A3(-9.6,11.2) A4(-8.8,11.2) A5(-8,11.2) A6(-7.2,11.2) A7(-6.4,11.2) A8(-5.6,11.2) A9(-4.8,11.2) A10(-4,11.2) A11(-3.2,11.2) A12(-2.4,11.2) A13(-1.6,11.2) A14(-0.8,11.2) A15(0,11.2) A16(0.8,11.2) A17(1.6,11.2) A18(2.4,11.2) A19(3.2,11.2) A20(4,11.2) A21(4.8,11.2) A22(5.6,11.2) A23(6.4,11.2) A24(7.2,11.2) A25(8,11.2) A26(8.8,11.2) A27(9.6,11.2) A28(10.4,11.2) AA1(-11.2,-4.8) AA2(-10.4,-4.8) AA3(-9.6,-4.8) AA4(-8.8,-4.8) AA5(-8,-4.8) AA6(-7.2,-4.8) AA7(-6.4,-4.8) AA8(-5.6,-4.8) AA9(-4.8,-4.8) AA10(-4,-4.8) AA11(-3.2,-4.8) AA12(-2.4,-4.8) AA13(-1.6,-4.8) AA14(-0.8,-4.8) AA15(0,-4.8) AA16(0.8,-4.8) AA17(1.6,-4.8) AA18(2.4,-4.8) AA19(3.2,-4.8) AA20(4,-4.8) AA21(4.8,-4.8) AA22(5.6,-4.8) AA23(6.4,-4.8) AA24(7.2,-4.8) AA25(8,-4.8) AA26(8.8,-4.8) AA27(9.6,-4.8) AA28(10.4,-4.8) AA29(11.2,-4.8) AB1(-11.2,-5.6) AB2(-10.4,-5.6) AB3(-9.6,-5.6) AB4(-8.8,-5.6) AB5(-8,-5.6) AB6(-7.2,-5.6) AB7(-6.4,-5.6) AB8(-5.6,-5.6) AB9(-4.8,-5.6) AB10(-4,-5.6) AB11(-3.2,-5.6) AB12(-2.4,-5.6) AB13(-1.6,-5.6) AB14(-0.8,-5.6) AB15(0,-5.6) AB16(0.8,-5.6) AB17(1.6,-5.6) AB18(2.4,-5.6) AB19(3.2,-5.6) AB20(4,-5.6) AB21(4.8,-5.6) AB22(5.6,-5.6) AB23(6.4,-5.6) AB24(7.2,-5.6) AB25(8,-5.6) AB26(8.8,-5.6) AB27(9.6,-5.6) AB28(10.4,-5.6) AB29(11.2,-5.6) AC1(-11.2,-6.4) AC2(-10.4,-6.4) AC3(-9.6,-6.4) AC4(-8.8,-6.4) AC5(-8,-6.4) AC6(-7.2,-6.4) AC7(-6.4,-6.4) AC8(-5.6,-6.4) AC9(-4.8,-6.4) AC10(-4,-6.4) AC11(-3.2,-6.4) AC12(-2.4,-6.4) AC13(-1.6,-6.4) AC14(-0.8,-6.4) AC15(0,-6.4) AC16(0.8,-6.4) AC17(1.6,-6.4) AC18(2.4,-6.4) AC19(3.2,-6.4) AC20(4,-6.4) AC21(4.8,-6.4) AC22(5.6,-6.4) AC23(6.4,-6.4) AC24(7.2,-6.4) AC25(8,-6.4) AC26(8.8,-6.4) AC27(9.6,-6.4) AC28(10.4,-6.4) AC29(11.2,-6.4) AD1(-11.2,-7.2) AD2(-10.4,-7.2) AD3(-9.6,-7.2) AD4(-8.8,-7.2) AD5(-8,-7.2) AD6(-7.2,-7.2) AD7(-6.4,-7.2) AD8(-5.6,-7.2) AD9(-4.8,-7.2) AD10(-4,-7.2) AD11(-3.2,-7.2) AD12(-2.4,-7.2) AD13(-1.6,-7.2) AD14(-0.8,-7.2) AD15(0,-7.2) AD16(0.8,-7.2) AD17(1.6,-7.2) AD18(2.4,-7.2) AD19(3.2,-7.2) AD20(4,-7.2) AD21(4.8,-7.2) AD22(5.6,-7.2) AD23(6.4,-7.2) AD24(7.2,-7.2) AD25(8,-7.2) AD26(8.8,-7.2) AD27(9.6,-7.2) AD28(10.4,-7.2) AD29(11.2,-7.2) AE1(-11.2,-8) AE2(-10.4,-8) AE3(-9.6,-8) AE4(-8.8,-8) AE5(-8,-8) AE6(-7.2,-8) AE7(-6.4,-8) AE8(-5.6,-8) AE9(-4.8,-8) AE10(-4,-8) AE11(-3.2,-8) AE12(-2.4,-8) AE13(-1.6,-8) AE14(-0.8,-8) AE15(0,-8) AE16(0.8,-8) AE17(1.6,-8) AE18(2.4,-8) AE19(3.2,-8) AE20(4,-8) AE21(4.8,-8) AE22(5.6,-8) AE23(6.4,-8) AE24(7.2,-8) AE25(8,-8) AE26(8.8,-8) AE27(9.6,-8) AE28(10.4,-8) AE29(11.2,-8) AF1(-11.2,-8.8) AF2(-10.4,-8.8) AF3(-9.6,-8.8) AF4(-8.8,-8.8) AF5(-8,-8.8) AF6(-7.2,-8.8) AF7(-6.4,-8.8) AF8(-5.6,-8.8) AF9(-4.8,-8.8) AF10(-4,-8.8) AF11(-3.2,-8.8) AF12(-2.4,-8.8) AF13(-1.6,-8.8) AF14(-0.8,-8.8) AF15(0,-8.8) AF16(0.8,-8.8) AF17(1.6,-8.8) AF18(2.4,-8.8) AF19(3.2,-8.8) AF20(4,-8.8) AF21(4.8,-8.8) AF22(5.6,-8.8) AF23(6.4,-8.8) AF24(7.2,-8.8) AF25(8,-8.8) AF26(8.8,-8.8) AF27(9.6,-8.8) AF28(10.4,-8.8) AF29(11.2,-8.8) AG1(-11.2,-9.6) AG2(-10.4,-9.6) AG3(-9.6,-9.6) AG4(-8.8,-9.6) AG5(-8,-9.6) AG6(-7.2,-9.6) AG7(-6.4,-9.6) AG8(-5.6,-9.6) AG9(-4.8,-9.6) AG10(-4,-9.6) AG11(-3.2,-9.6) AG12(-2.4,-9.6) AG13(-1.6,-9.6) AG14(-0.8,-9.6) AG15(0,-9.6) AG16(0.8,-9.6) AG17(1.6,-9.6) AG18(2.4,-9.6) AG19(3.2,-9.6) AG20(4,-9.6) AG21(4.8,-9.6) AG22(5.6,-9.6) AG23(6.4,-9.6) AG24(7.2,-9.6) AG25(8,-9.6) AG26(8.8,-9.6) AG27(9.6,-9.6) AG28(10.4,-9.6) AG29(11.2,-9.6) AH1(-11.2,-10.4) AH2(-10.4,-10.4) AH3(-9.6,-10.4) AH4(-8.8,-10.4) AH5(-8,-10.4) AH6(-7.2,-10.4) AH7(-6.4,-10.4) AH8(-5.6,-10.4) AH9(-4.8,-10.4) AH10(-4,-10.4) AH11(-3.2,-10.4) AH12(-2.4,-10.4) AH13(-1.6,-10.4) AH14(-0.8,-10.4) AH15(0,-10.4) AH16(0.8,-10.4) AH17(1.6,-10.4) AH18(2.4,-10.4) AH19(3.2,-10.4) AH20(4,-10.4) AH21(4.8,-10.4) AH22(5.6,-10.4) AH23(6.4,-10.4) AH24(7.2,-10.4) AH25(8,-10.4) AH26(8.8,-10.4) AH27(9.6,-10.4) AH28(10.4,-10.4) AH29(11.2,-10.4) AJ2(-10.4,-11.2) AJ3(-9.6,-11.2) AJ4(-8.8,-11.2) AJ5(-8,-11.2) AJ6(-7.2,-11.2) AJ7(-6.4,-11.2) AJ8(-5.6,-11.2) AJ9(-4.8,-11.2) AJ10(-4,-11.2) AJ11(-3.2,-11.2) AJ12(-2.4,-11.2) AJ13(-1.6,-11.2) AJ14(-0.8,-11.2) AJ15(0,-11.2) AJ16(0.8,-11.2) AJ17(1.6,-11.2) AJ18(2.4,-11.2) AJ19(3.2,-11.2) AJ20(4,-11.2) AJ21(4.8,-11.2) AJ22(5.6,-11.2) AJ23(6.4,-11.2) AJ24(7.2,-11.2) AJ25(8,-11.2) AJ26(8.8,-11.2) AJ27(9.6,-11.2) AJ28(10.4,-11.2) AJ29(11.2,-11.2) B1(-11.2,10.4) B2(-10.4,10.4) B3(-9.6,10.4) B4(-8.8,10.4) B5(-8,10.4) B6(-7.2,10.4) B7(-6.4,10.4) B8(-5.6,10.4) B9(-4.8,10.4) B10(-4,10.4) B11(-3.2,10.4) B12(-2.4,10.4) B13(-1.6,10.4) B14(-0.8,10.4) B15(0,10.4) B16(0.8,10.4) B17(1.6,10.4) B18(2.4,10.4) B19(3.2,10.4) B20(4,10.4) B21(4.8,10.4) B22(5.6,10.4) B23(6.4,10.4) B24(7.2,10.4) B25(8,10.4) B26(8.8,10.4) B27(9.6,10.4) B28(10.4,10.4) B29(11.2,10.4) C1(-11.2,9.6) C2(-10.4,9.6) C3(-9.6,9.6) C4(-8.8,9.6) C5(-8,9.6) C6(-7.2,9.6) C7(-6.4,9.6) C8(-5.6,9.6) C9(-4.8,9.6) C10(-4,9.6) C11(-3.2,9.6) C12(-2.4,9.6) C13(-1.6,9.6) C14(-0.8,9.6) C15(0,9.6) C16(0.8,9.6) C17(1.6,9.6) C18(2.4,9.6) C19(3.2,9.6) C20(4,9.6) C21(4.8,9.6) C22(5.6,9.6) C23(6.4,9.6) C24(7.2,9.6) C25(8,9.6) C26(8.8,9.6) C27(9.6,9.6) C28(10.4,9.6) C29(11.2,9.6) D1(-11.2,8.8) D2(-10.4,8.8) D3(-9.6,8.8) D4(-8.8,8.8) D5(-8,8.8) D6(-7.2,8.8) D7(-6.4,8.8) D8(-5.6,8.8) D9(-4.8,8.8) D10(-4,8.8) D11(-3.2,8.8) D12(-2.4,8.8) D13(-1.6,8.8) D14(-0.8,8.8) D15(0,8.8) D16(0.8,8.8) D17(1.6,8.8) D18(2.4,8.8) D19(3.2,8.8) D20(4,8.8) D21(4.8,8.8) D22(5.6,8.8) D23(6.4,8.8) D24(7.2,8.8) D25(8,8.8) D26(8.8,8.8) D27(9.6,8.8) D28(10.4,8.8) D29(11.2,8.8) E1(-11.2,8) E2(-10.4,8) E3(-9.6,8) E4(-8.8,8) E5(-8,8) E6(-7.2,8) E7(-6.4,8) E8(-5.6,8) E9(-4.8,8) E10(-4,8) E11(-3.2,8) E12(-2.4,8) E13(-1.6,8) E14(-0.8,8) E15(0,8) E16(0.8,8) E17(1.6,8) E18(2.4,8) E19(3.2,8) E20(4,8) E21(4.8,8) E22(5.6,8) E23(6.4,8) E24(7.2,8) E25(8,8) E26(8.8,8) E27(9.6,8) E28(10.4,8) E29(11.2,8) F1(-11.2,7.2) F2(-10.4,7.2) F3(-9.6,7.2) F4(-8.8,7.2) F5(-8,7.2) F6(-7.2,7.2) F7(-6.4,7.2) F8(-5.6,7.2) F9(-4.8,7.2) F10(-4,7.2) F11(-3.2,7.2) F12(-2.4,7.2) F13(-1.6,7.2) F14(-0.8,7.2) F15(0,7.2) F16(0.8,7.2) F17(1.6,7.2) F18(2.4,7.2) F19(3.2,7.2) F20(4,7.2) F21(4.8,7.2) F22(5.6,7.2) F23(6.4,7.2) F24(7.2,7.2) F25(8,7.2) F26(8.8,7.2) F27(9.6,7.2) F28(10.4,7.2) F29(11.2,7.2) G1(-11.2,6.4) G2(-10.4,6.4) G3(-9.6,6.4) G4(-8.8,6.4) G5(-8,6.4) G6(-7.2,6.4) G7(-6.4,6.4) G8(-5.6,6.4) G9(-4.8,6.4) G10(-4,6.4) G11(-3.2,6.4) G12(-2.4,6.4) G13(-1.6,6.4) G14(-0.8,6.4) G15(0,6.4) G16(0.8,6.4) G17(1.6,6.4) G18(2.4,6.4) G19(3.2,6.4) G20(4,6.4) G21(4.8,6.4) G22(5.6,6.4) G23(6.4,6.4) G24(7.2,6.4) G25(8,6.4) G26(8.8,6.4) G27(9.6,6.4) G28(10.4,6.4) G29(11.2,6.4) H1(-11.2,5.6) H2(-10.4,5.6) H3(-9.6,5.6) H4(-8.8,5.6) H5(-8,5.6) H6(-7.2,5.6) H7(-6.4,5.6) H8(-5.6,5.6) H9(-4.8,5.6) H10(-4,5.6) H11(-3.2,5.6) H12(-2.4,5.6) H13(-1.6,5.6) H14(-0.8,5.6) H15(0,5.6) H16(0.8,5.6) H17(1.6,5.6) H18(2.4,5.6) H19(3.2,5.6) H20(4,5.6) H21(4.8,5.6) H22(5.6,5.6) H23(6.4,5.6) H24(7.2,5.6) H25(8,5.6) H26(8.8,5.6) H27(9.6,5.6) H28(10.4,5.6) H29(11.2,5.6) J1(-11.2,4.8) J2(-10.4,4.8) J3(-9.6,4.8) J4(-8.8,4.8) J5(-8,4.8) J6(-7.2,4.8) J7(-6.4,4.8) J8(-5.6,4.8) J9(-4.8,4.8) J10(-4,4.8) J11(-3.2,4.8) J12(-2.4,4.8) J13(-1.6,4.8) J14(-0.8,4.8) J15(0,4.8) J16(0.8,4.8) J17(1.6,4.8) J18(2.4,4.8) J19(3.2,4.8) J20(4,4.8) J21(4.8,4.8) J22(5.6,4.8) J23(6.4,4.8) J24(7.2,4.8) J25(8,4.8) J26(8.8,4.8) J27(9.6,4.8) J28(10.4,4.8) J29(11.2,4.8) K1(-11.2,4) K2(-10.4,4) K3(-9.6,4) K4(-8.8,4) K5(-8,4) K6(-7.2,4) K7(-6.4,4) K8(-5.6,4) K9(-4.8,4) K10(-4,4) K11(-3.2,4) K12(-2.4,4) K13(-1.6,4) K14(-0.8,4) K15(0,4) K16(0.8,4) K17(1.6,4) K18(2.4,4) K19(3.2,4) K20(4,4) K21(4.8,4) K22(5.6,4) K23(6.4,4) K24(7.2,4) K25(8,4) K26(8.8,4) K27(9.6,4) K28(10.4,4) K29(11.2,4) L1(-11.2,3.2) L2(-10.4,3.2) L3(-9.6,3.2) L4(-8.8,3.2) L5(-8,3.2) L6(-7.2,3.2) L7(-6.4,3.2) L8(-5.6,3.2) L9(-4.8,3.2) L10(-4,3.2) L11(-3.2,3.2) L12(-2.4,3.2) L13(-1.6,3.2) L14(-0.8,3.2) L15(0,3.2) L16(0.8,3.2) L17(1.6,3.2) L18(2.4,3.2) L19(3.2,3.2) L20(4,3.2) L21(4.8,3.2) L22(5.6,3.2) L23(6.4,3.2) L24(7.2,3.2) L25(8,3.2) L26(8.8,3.2) L27(9.6,3.2) L28(10.4,3.2) L29(11.2,3.2) M1(-11.2,2.4) M2(-10.4,2.4) M3(-9.6,2.4) M4(-8.8,2.4) M5(-8,2.4) M6(-7.2,2.4) M7(-6.4,2.4) M8(-5.6,2.4) M9(-4.8,2.4) M10(-4,2.4) M14(-0.8,2.4) M15(0,2.4) M16(0.8,2.4) M17(1.6,2.4) M18(2.4,2.4) M19(3.2,2.4) M20(4,2.4) M21(4.8,2.4) M22(5.6,2.4) M23(6.4,2.4) M24(7.2,2.4) M25(8,2.4) M26(8.8,2.4) M27(9.6,2.4) M28(10.4,2.4) M29(11.2,2.4) N1(-11.2,1.6) N2(-10.4,1.6) N3(-9.6,1.6) N4(-8.8,1.6) N5(-8,1.6) N6(-7.2,1.6) N7(-6.4,1.6) N8(-5.6,1.6) N9(-4.8,1.6) N10(-4,1.6) N14(-0.8,1.6) N15(0,1.6) N16(0.8,1.6) N17(1.6,1.6) N18(2.4,1.6) N19(3.2,1.6) N20(4,1.6) N21(4.8,1.6) N22(5.6,1.6) N23(6.4,1.6) N24(7.2,1.6) N25(8,1.6) N26(8.8,1.6) N27(9.6,1.6) N28(10.4,1.6) N29(11.2,1.6) P1(-11.2,0.8) P2(-10.4,0.8) P3(-9.6,0.8) P4(-8.8,0.8) P5(-8,0.8) P6(-7.2,0.8) P7(-6.4,0.8) P8(-5.6,0.8) P9(-4.8,0.8) P10(-4,0.8) P11(-3.2,0.8) P12(-2.4,0.8) P13(-1.6,0.8) P14(-0.8,0.8) P15(0,0.8) P16(0.8,0.8) P17(1.6,0.8) P18(2.4,0.8) P19(3.2,0.8) P20(4,0.8) P21(4.8,0.8) P22(5.6,0.8) P23(6.4,0.8) P24(7.2,0.8) P25(8,0.8) P26(8.8,0.8) P27(9.6,0.8) P28(10.4,0.8) P29(11.2,0.8) R1(-11.2,0) R2(-10.4,0) R3(-9.6,0) R4(-8.8,0) R5(-8,0) R6(-7.2,0) R7(-6.4,0) R8(-5.6,0) R9(-4.8,0) R10(-4,0) R11(-3.2,0) R12(-2.4,0) R13(-1.6,0) R14(-0.8,0) R15(0,0) R16(0.8,0) R17(1.6,0) R18(2.4,0) R19(3.2,0) R20(4,0) R21(4.8,0) R22(5.6,0) R23(6.4,0) R24(7.2,0) R25(8,0) R26(8.8,0) R27(9.6,0) R28(10.4,0) R29(11.2,0) T1(-11.2,-0.8) T2(-10.4,-0.8) T3(-9.6,-0.8) T4(-8.8,-0.8) T5(-8,-0.8) T6(-7.2,-0.8) T7(-6.4,-0.8) T8(-5.6,-0.8) T9(-4.8,-0.8) T10(-4,-0.8) T14(-0.8,-0.8) T15(0,-0.8) T16(0.8,-0.8) T17(1.6,-0.8) T18(2.4,-0.8) T19(3.2,-0.8) T20(4,-0.8) T21(4.8,-0.8) T22(5.6,-0.8) T23(6.4,-0.8) T24(7.2,-0.8) T25(8,-0.8) T26(8.8,-0.8) T27(9.6,-0.8) T28(10.4,-0.8) T29(11.2,-0.8) U1(-11.2,-1.6) U2(-10.4,-1.6) U3(-9.6,-1.6) U4(-8.8,-1.6) U5(-8,-1.6) U6(-7.2,-1.6) U7(-6.4,-1.6) U8(-5.6,-1.6) U9(-4.8,-1.6) U10(-4,-1.6) U14(-0.8,-1.6) U15(0,-1.6) U16(0.8,-1.6) U17(1.6,-1.6) U18(2.4,-1.6) U19(3.2,-1.6) U20(4,-1.6) U21(4.8,-1.6) U22(5.6,-1.6) U23(6.4,-1.6) U24(7.2,-1.6) U25(8,-1.6) U26(8.8,-1.6) U27(9.6,-1.6) U28(10.4,-1.6) U29(11.2,-1.6) V1(-11.2,-2.4) V2(-10.4,-2.4) V3(-9.6,-2.4) V4(-8.8,-2.4) V5(-8,-2.4) V6(-7.2,-2.4) V7(-6.4,-2.4) V8(-5.6,-2.4) V9(-4.8,-2.4) V10(-4,-2.4) V11(-3.2,-2.4) V12(-2.4,-2.4) V13(-1.6,-2.4) V14(-0.8,-2.4) V15(0,-2.4) V16(0.8,-2.4) V17(1.6,-2.4) V18(2.4,-2.4) V19(3.2,-2.4) V20(4,-2.4) V21(4.8,-2.4) V22(5.6,-2.4) V23(6.4,-2.4) V24(7.2,-2.4) V25(8,-2.4) V26(8.8,-2.4) V27(9.6,-2.4) V28(10.4,-2.4) V29(11.2,-2.4) W1(-11.2,-3.2) W2(-10.4,-3.2) W3(-9.6,-3.2) W4(-8.8,-3.2) W5(-8,-3.2) W6(-7.2,-3.2) W7(-6.4,-3.2) W8(-5.6,-3.2) W9(-4.8,-3.2) W10(-4,-3.2) W11(-3.2,-3.2) W12(-2.4,-3.2) W13(-1.6,-3.2) W14(-0.8,-3.2) W15(0,-3.2) W16(0.8,-3.2) W17(1.6,-3.2) W18(2.4,-3.2) W19(3.2,-3.2) W20(4,-3.2) W21(4.8,-3.2) W22(5.6,-3.2) W23(6.4,-3.2) W24(7.2,-3.2) W25(8,-3.2) W26(8.8,-3.2) W27(9.6,-3.2) W28(10.4,-3.2) W29(11.2,-3.2) Y1(-11.2,-4) Y2(-10.4,-4) Y3(-9.6,-4) Y4(-8.8,-4) Y5(-8,-4) Y6(-7.2,-4) Y7(-6.4,-4) Y8(-5.6,-4) Y9(-4.8,-4) Y10(-4,-4) Y11(-3.2,-4) Y12(-2.4,-4) Y13(-1.6,-4) Y14(-0.8,-4) Y15(0,-4) Y16(0.8,-4) Y17(1.6,-4) Y18(2.4,-4) Y19(3.2,-4) Y20(4,-4) Y21(4.8,-4) Y22(5.6,-4) Y23(6.4,-4) Y24(7.2,-4) Y25(8,-4) Y26(8.8,-4) Y27(9.6,-4) Y28(10.4,-4) Y29(11.2,-4)
